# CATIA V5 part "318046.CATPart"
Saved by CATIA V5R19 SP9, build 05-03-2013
Part number: 318046
Source: Unknown
Bounding box of the stored display mesh (mm): x -34.399 to 267.6, y -226.99 to -194.518, z 435 to 559
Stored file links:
  D:\16-SIL\kale oto\R19_V2\318046.CATPart
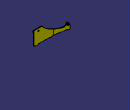
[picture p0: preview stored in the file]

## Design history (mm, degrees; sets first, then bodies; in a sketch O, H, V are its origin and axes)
Body1 "120\\23\\MANIFOLD_SOLID_BREP #40514" (main body)
  Solid1: solid without history
Body2 "241\\222\\MANIFOLD_SOLID_BREP #153170"
  Solid2: solid without history
Body3 "241\\221\\MANIFOLD_SOLID_BREP #154205"
  Solid3: solid without history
